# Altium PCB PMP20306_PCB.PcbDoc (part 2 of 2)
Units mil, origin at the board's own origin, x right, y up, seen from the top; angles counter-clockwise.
Board outline 1000 x 1500 mil, 4 copper layers (Top Layer, Signal Layer 1, Signal Layer 2, Bottom Layer), stack 42.6 mil thick; 50 components, 30 nets, 132 pads, 42 vias.
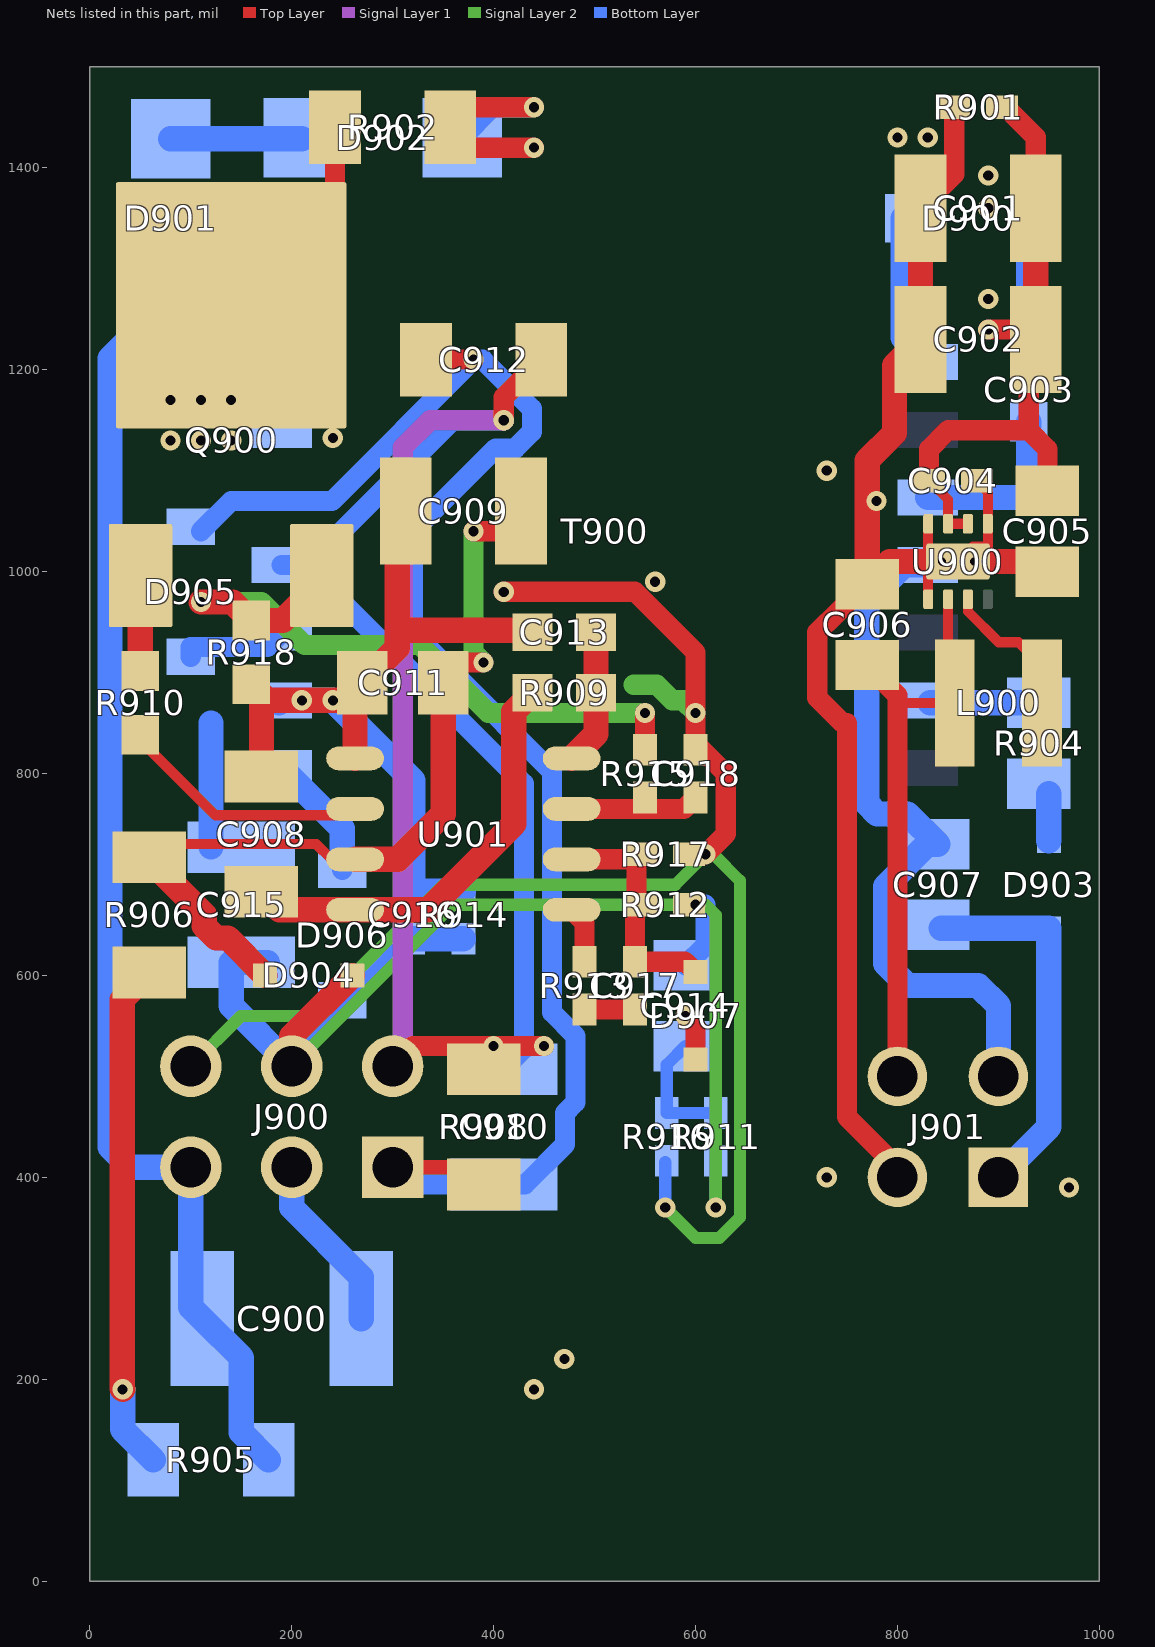
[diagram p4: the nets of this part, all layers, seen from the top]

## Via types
v1: diameter 20, hole 10, Top Layer to Bottom Layer, 40 vias
v2: diameter 19.68, hole 7.87, Top Layer to Bottom Layer, 2 vias

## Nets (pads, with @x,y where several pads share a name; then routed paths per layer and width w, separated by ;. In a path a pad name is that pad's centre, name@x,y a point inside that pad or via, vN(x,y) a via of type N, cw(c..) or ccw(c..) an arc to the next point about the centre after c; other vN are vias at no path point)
5V: C906.1 J901.4 L900.2 U900.6 | length 551.7
  Top Layer w10: 800,877.5 807.5,870 L900.2@856.69,870 ; L900.2@850.16,886.54 U900.6@850.16,972.6
  Top Layer w20: C906.1@780,897.5 800,877.5 J901.4@800,500
12VPH: C910.2 C912.1 D905.1 J900.1 R908.2 | length 1636.9
  Top Layer w14: J900.1@300,410 392.91,410 R908.2@410,392.91
  Top Layer w20: C912.1@332.91,1210 v1(380,1210)
  Bottom Layer w20: D905.1@110,1040 140,1070 240,1070 v1(380,1210) 389.42,1210 437.87,1161.55 437.87,1138.45 421.55,1122.13 402.13,1122.13 320,1040 320,940 410,850 410,849.42 457.87,801.55 457.87,563.23 481.02,540.08 481.02,474.09 470.55,463.62 470.55,432.44 431.03,392.91 C910.2@410,392.91 317.09,392.91 J900.1@300,410
12VPL: C914.1 C915.2 C916.1 D904.2 D906.1 J900.4 R911.2 R912.2 R914.2 | length 1405.1
  Top Layer w25: J900.4@200,510 200,539.76 D904.2@260.24,600
  Signal Layer 2 w12: J900.4@200,510 360,670 610,670 620,660 v1(620,370)
  Bottom Layer w12: v1(620,370) R911.2@620,416.38
  Bottom Layer w20: C914.1@590,610 610,630 610,670
  Bottom Layer w25: C915.2@175.91,612.91 140,612.91 140,570 J900.4@200,510 200,525.53 D906.1@250,575.53 310.85,636.38 R914.2@370,636.38
  other v1: 600,670
B+: C900.1 D901.2 J900.5 R905.1 T900.8 | length 1387.3
  Bottom Layer w25: D901.2@80,1271.26 20,1211.26 20,430 40,410 J900.5@100,410 100,271.26 C900.1@111.26,260 150,221.26 150,147.09 R905.1@177.09,120 ; D901.2@80.63,1270.63 84.5,1274.5 T900.8@190,1274.5
GND_PRI: C900.2 C908.2 C909.1 C911.2 C913.1 C915.1 C916.2 C918.2 J900.3 J900.6 R914.1 R916.1 R917.1 R918.1 T900.2 U901.5 | length 2808.8
  Top Layer w20: v1(410,980) 540,980 600,920 v1(600,860) C918.2@600,823.62 606.38,823.62 630,800 630,740 v1(610,720)
  Top Layer w25: C908.2@170,797.09 R918.1@170,878.5 ; R918.1@176,872.5 v1(240.7,872.5) 252.5,872.5 C911.2@262.72,882.72 ; U901.5@262.72,815 C911.2@262.72,882.72 ; C909.1@304.63,1051.71 304.63,924.63 C911.2@270,890 C911.2@262.72,882.72 ; 312.75,941.87 438.5,941.87 C913.1@438.5,940
  Signal Layer 2 w12: J900.6@100,510 149.76,559.76 220,559.76 350.11,689.87 579.87,689.87 v1(610,720) 617.75,720 643.87,693.87 643.87,360.11 623.76,340 600,340 v1(570,370)
  Signal Layer 2 w20: 538.45,887.87 561.55,887.87 576.92,872.5 587.5,872.5 v1(600,860)
  Bottom Layer w12: v1(570,370) R916.1@570,414.92
  Bottom Layer w25: 120,850 120,727.13 C915.1@120.04,727.09 ; T900.2@187.5,870 T900.2@190,872.5 v1(240.7,872.5) 320,793.2 C916.2@320,683.62 R914.1@370,683.62 ; J900.3@200,410 200,370 268.74,301.26 C900.2@268.74,260
  other v1: 440,190 470,220 210,872.5 560,990
HSS: C910.1 C912.2 J900.2 R908.1 T900.4 | length 1824.6
  Top Layer w20: J900.2@300,510 320,530 v1(400,530) v1(450,530) ; v1(410,1150) 410,1172.91 C912.2@447.09,1210
  Signal Layer 1 w20: J900.2@310,520 310,1122.99 337.01,1150 v1(410,1150)
  Bottom Layer w20: T900.4@190,1006.5 T900.4@213.5,1006.5 ; C910.1@410,507.09 430,527.09 430,790 T900.4@213.5,1006.5 ; v1(410,1150) 359.42,1150 215.92,1006.5 T900.4@213.5,1006.5
NetC901_2: C901.2 C902.2 C903.1 C904.1 C905.1 D900.1 R901.2 U900.2 U900.3 | length 755.6
  Top Layer w10: C904.1@831.38,1090 850,1071.38 850,1047.56 U900.3@850.16,1047.4 U900.2@869.84,1047.4
  Top Layer w20: C904.1@831.38,1090 831.38,1121.38 850,1140 930,1140 ; v1(890,1240) C902.2@927.09,1240 ; R901.2@903.62,1460 907.5,1460 937.09,1430.41 C901.2@937.09,1360 ; C902.2@930,1222.91 930,1140 ; C905.1@948.54,1080 948.54,1121.46 930,1140
  Top Layer w25: C902.2@937.09,1250 C901.2@937.09,1360
  Bottom Layer w25: C903.1@930,1211.5 D900.1@930,1345.53
  other v1: 890,1270 890,1360 890,1392.5
NetC908_1: C908.1 R909.2 U901.8 | length 430.3
  Top Layer w25: C908.1@170,682.91 187.91,665 U901.8@262.72,665 335,665 420,750 420,861.5 R909.2@438.5,880
NetC909_2: C909.2 C911.1 D904.1 R906.2 U901.7 | length 804
  Top Layer w10: R906.2@58.8,717.09 71.71,730 224.33,730 239.33,715 U901.7@262.72,715
  Top Layer w20: C911.1@370,910 v1(390,910) ; v1(380,1040) C909.2@407.09,1040
  Top Layer w25: R906.2@58.8,717.09 58.8,714.82 113.21,660.41 113.21,648.88 125.14,636.95 136.67,636.95 D904.1@173.62,600 ; U901.7@262.72,715 305,715 350,760 C911.1@350,890
  Signal Layer 2 w20: v1(380,1040) 380,920 v1(390,910)
NetC913_2: C913.2 R909.1 U901.4 | length 135
  Top Layer w25: U901.4@477.28,815 501.5,839.21 R909.1@501.5,880 C913.2@501.5,940
NetC914_2: C914.2 D907.2 R911.1 R916.2 | length 170.1
  Top Layer w20: v1(590,560) 600,550 D907.2@600,516.69
  Bottom Layer w12: C914.2@590,530 571.46,511.46 R916.2@571.46,463.62 R911.1@620,463.62
NetC917_1: C917.1 R913.1 | length 50
  Top Layer w20: R913.1@490,566.38 C917.1@540,566.38
NetC917_2: C917.2 D907.1 R912.1 R917.2 U901.2 | length 218.4
  Top Layer w20: U901.2@477.28,715 541.38,715 R912.1@541.38,675 ; R912.1@540,663.62 C917.2@540,613.62 589.68,613.62 D907.1@600,603.31
NetC918_1: C918.1 R915.1 U901.3 | length 127.4
  Top Layer w20: U901.3@477.28,765 588.62,765 C918.1@600,776.38
NetD900_2: D900.2 T900.10 | length 152.6
  Bottom Layer w25: D900.2@805.53,1350 805.53,1231.97 T900.10@830,1207.5
NetD901_1: D901.1 D902.1 | length 130
  Bottom Layer w25: D901.1@80,1428.74 D902.1@210,1428.74
NetD902_2: D902.2 R902.1 | length 209.5
  Top Layer w20: R902.1@377.09,1420 v1(440,1420) ; R902.1@377.09,1460 v1(440,1460)
  Bottom Layer w20: D902.2@368.74,1430 398.74,1460 v1(440,1460)
NetD903_2: D903.2 R904.1 | length 46.7
  Bottom Layer w25: D903.2@950,733.31 R904.1@950,780
NetD905_2: D905.2 T900.3 | length 111.8
  Bottom Layer w20: D905.2@100,915.53 100,925.34 175.84,925.34 T900.3@190,939.5 T900.3@183.88,939.5
NetD906_2: D906.2 T900.1 | length 125.9
  Bottom Layer w20: D906.2@250,704.47 D906.2@250,715
  Bottom Layer w25: T900.1@190,805.5 250,745.5 D906.2@250,715
NetL900_1: L900.1 U900.7 | length 144.6
  Top Layer w10: U900.7@869.84,972.6 869.84,960.47 900.31,930 920,930 943.31,906.69 L900.1@943.31,870
NetQ900_1: Q900.1 R910.2 | length 94.7
  Top Layer w25: R910.2@50,901.5 50,995.91 Q900.1@50.24,996.14
NetQ900_3: Q900.3 R915.2 R918.2 | length 671.6
  Top Layer w20: R915.2@550,823.62 v1(550,860)
  Top Layer w25: v1(110,970) 141.5,970 R918.2@160,951.5 191.5,951.5 229.76,989.76 Q900.3@229.76,996.14
  Signal Layer 2 w20: v1(110,970) 170,970 212.83,927.17 327.46,927.17 394.63,860 v1(550,860)
NetQ900_4: Q900.4 R902.2 T900.6 | length 73.2
  Top Layer w20: Q900.4@242.91,1366.77 R902.2@242.91,1440
  other v1: 80,1130 110,1130 140,1130 240.7,1132.5 80,1170 110,1170 140,1170
NetR904_2: R904.2 T900.15 | length 107.5
  Bottom Layer w25: T900.15@832.5,870 R904.2@940,870
NetR905_2: R905.2 R906.1 | length 491.5
  Top Layer w25: v1(32.5,190) 31.99,190.51 31.99,576.1 R906.1@47.94,592.06
  Bottom Layer w25: v1(32.5,190) 32.5,150.41 R905.2@62.91,120
NetR910_1: R910.1 U901.6 | length 251.7
  Top Layer w10: R910.1@50,838.5 50,832.91 124.29,758.62 256.34,758.62 U901.6@262.72,765
NetR913_2: R913.2 U901.1 | length 56.6
  Top Layer w20: U901.1@477.28,665 490,652.28 R913.2@490,613.62
SGND: C901.1 C902.1 C903.2 C904.2 C905.2 C906.2 C907.1 J901.2 J901.3 R901.1 T900.12 T900.13 U900.1 U900.4 U900.5 U900.9 | length 2373.3
  Top Layer w10: U900.5@830.47,972.6 830.47,1009.53 830,1010 830.47,1010.47 U900.4@830.47,1047.4 ; U900.9@860,1010 874.69,1024.69 889.53,1024.69 U900.1@889.53,1047.4 889.53,1079.09 C904.2@878.62,1090
  Top Layer w20: C906.2@770,987.5 768.76,987.5 731.63,950.38 731.1,950.38 720.63,939.91 720.63,875.1 745.73,850 750,850 750,460 800,410 J901.3@800,400 ; C901.1@822.91,1360 856.38,1393.46 R901.1@856.38,1460
  Top Layer w25: C901.1@822.91,1360 C902.1@822.91,1230 797.09,1204.17 797.09,1137.09 770,1110 C906.2@770,987.5 792.5,1010 830,1010 v2(844.25,1010) U900.9@860,1010 ; v2(875.75,1010) C905.2@938.54,1010
  Bottom Layer w25: T900.13@830,1006.5 806.5,1006.5 769.64,969.64 769.64,770.36 780,760 810,760 C907.1@840,730 830,730 788.13,688.13 788.13,611.87 810,590 880,590 900,570 J901.2@900,500 ; T900.12@830,1073.5 923.5,1073.5 930,1080 C903.2@930,1148.5
  other v1: 970,390 730,400 779.29,1070 730,1100 800,1430 830,1430
VMON: C907.2 D903.1 J901.1 | length 374.1
  Bottom Layer w25: C907.2@843.31,646.69 D903.1@950,646.69 950,450 J901.1@900,400
pads on no net: T900.7 T900.11 T900.14 T900.16 U900.8

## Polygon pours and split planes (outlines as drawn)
GND_PRI on Top Layer "GND_PRI" (solid, remove dead copper, pour order 40): 260,170 230,200 230,280 60,450 60,560 60,920 80,940 150,940 197.48,940 287.48,1030 550,1030 650,930 650,900 650,370 450,170
SGND on Top Layer "SGND" (solid, remove dead copper, pour order 26): 730,370 710,390 710,420 710,1098.5 780,1168.5 780,1430 840,1490 970,1490 990,1470 990,1060 990,390 970,370
5V on Top Layer "5V" (solid, remove dead copper, pour order 24): 850.16,972.6 850,972.44 850,910 850,780 850,670 850,504.25 815.75,470 790,470 770,490 770,520 780,530 780,570 780,897.5 780,921.91 781.91,921.91 800,940 810,950 830,950 840,960 840,970 847.56,970 850.16,972.6
NetL900_1 on Top Layer "L900_1" (solid, remove dead copper, pour order 22): 960,810 930,810 920,810 910,820 900,830 900,870 900,920 870,950 869.84,950.16 869.84,972.6 876.06,972.6 880,968.66 898.66,950 910,950 950,950 960,940
NetC901_2 on Top Layer "C901_2" (solid, remove dead copper, pour order 20): 980,1060 990,1070 990,1220 990,1470 970,1490 940,1490 910,1490 890,1470 890,1460 890,1410 880,1400 880,1380 880,1320 880,1180 820,1120 820,1090 820,1077.56 850,1047.56 850.16,1047.4 869.84,1047.4 869.84,1059.84 870,1060 860,1070 860,1090 860,1101.65 870,1111.65 890,1111.65 898.35,1111.65 950,1060
NetD902_2 on Top Layer "D902_2" (solid, remove dead copper, pour order 4): 320,1470 340,1490 350,1490 450,1490 470,1470 470,1450 470,1410 450,1390 340,1390 320,1410
NetQ900_3 on Top Layer "Q900_3" (solid, remove dead copper, pour order 2): 260,1040 260,950 110,950 100,960 100,980 110,990 160,1040 190,1040
NetQ900_4 on Top Layer "Q900_4" (solid, remove dead copper, pour order 0): 30,1110 10,1130 10,1340 10,1470 30,1490 70,1490 260,1490 280,1470 280,1450 280,1411.73 250.24,1381.97 250,1381.73 250,1350 250,1130 230,1110
SGND on Bottom Layer "SGND" (solid, remove dead copper, pour order 42): 730,370 710,390 710,420 710,1098.5 780,1168.5 780,1430 840,1490 970,1490 990,1470 990,1060 990,390 970,370
GND_PRI on Bottom Layer "GND_PRI" (solid, remove dead copper, pour order 34): 260,170 230,200 230,280 60,450 60,560 60,920 80,940 150,940 270,940 330,1000 340,1010 360,1010 570,1010 650,930 650,900 650,370 450,170
HSS on Bottom Layer "HSS" (solid, remove dead copper, pour order 30): 170,1014.5 170,1030 180,1040 200,1040 234.92,1040 244.92,1050 354.92,1160 390,1160 400,1160 410,1150 410,1140 400,1140 370,1110 340,1080 304.63,1044.63 304.63,980 304.63,933.92 320,918.54 440,798.54 440,620 440,560 460,540 460,516.93 460,500 450,490 400,490 390,480 330,480 280,480 270,490 270,520 290,540 320,540 350,540 410,600 410,700 410,761.46 310,861.46 170,1001.46 170,1006.5
GND_PRI on Bottom Layer "GND_PRI" (solid, remove dead copper, pour order 28): 240,190 230,200 230,210 230,280 50,460 50,630 50,881.3 68.7,900 160,900 240,900 330,810 380,760 380,673.78 380,670 240,530 240,400 240,380 250,370 284.49,335.51 284.49,270 284.49,200 280,195.51 280,200 273.07,193.07 270,190
NetC901_2 on Bottom Layer "C901_2" (solid, remove dead copper, pour order 18): 920,1200 958.54,1200 970,1200 990,1220 990,1240 990,1400 980,1410 890,1410 880,1400 880,1350 880,1221.46 901.46,1200
NetD900_2 on Bottom Layer "D900_2" (solid, remove dead copper, pour order 16): 860,1190 860,1220 860,1340 820,1380 813.07,1380 780,1380 770,1370 770,1360 770,1200 780,1190
12VPL on Bottom Layer "12VPL" (solid, remove dead copper, pour order 14): 180,490 170,500 170,520 130,560 100,590 100,603.07 100,610 140,650 160,650 370,650 380,640 380,630 380,622 370,612 358,600 310,600 240,530 200,490
NetQ900_4 on Bottom Layer "Q900_4" (solid, remove dead copper, pour order 12): 80,1110 70,1120 70,1170 80,1180 90,1180 150,1180 170,1160 230,1160 240,1160 250,1150 250,1140 250,1130 240,1120 230,1110
NetD902_2 on Bottom Layer "D902_2" (solid, remove dead copper, pour order 10): 340,1490 320,1470 320,1460 320,1390 321.5,1390 340,1371.5 390,1371.5 441.5,1371.5 460,1390 460,1400 460,1470 440,1490
NetD901_1 on Bottom Layer "D901_1" (solid, remove dead copper, pour order 8): 30,1490 10,1470 10,1440 10,1410 10,1390 30,1370 40,1370 250,1370 270,1390 270,1404.57 270,1470 250,1490
B+ on Bottom Layer "B+" (solid, remove dead copper, pour order 6): 230,1260 220,1250 200,1250 150,1250 140.08,1250 120,1229.92 90,1229.92 49.92,1229.92 20,1200 10,1200 10,1230 10,1290 10,1310 20,1320 50,1320 220,1320 230,1310
SGND on Signal Layer 1 "SGND" (solid, remove dead copper, pour order 46): 730,370 710,390 710,420 710,1098.5 780,1168.5 780,1430 840,1490 970,1490 990,1470 990,1060 990,390 970,370
GND_PRI on Signal Layer 1 "GND_PRI" (solid, remove dead copper, pour order 38): 260,170 230,200 230,280 60,450 60,560 60,920 80,940 150,940 270,940 330,1000 340,1010 360,1010 570,1010 650,930 650,900 650,370 450,170
HSS on Signal Layer 1 "HSS" (solid, remove dead copper, pour order 32): 420,1170 430,1160 430,1150 430,1140 420,1130 380,1090 360,1070 360,1020 360,698.35 468.35,590 468.35,560 468.35,498.35 450,480 420,480 280,480 270,490 270,510 270,1140 300,1170
SGND on Signal Layer 2 "SGND" (solid, remove dead copper, pour order 44): 730,370 710,390 710,420 710,1098.5 780,1168.5 780,1430 840,1490 970,1490 990,1470 990,1060 990,390 970,370
GND_PRI on Signal Layer 2 "GND_PRI" (solid, remove dead copper, pour order 36): 260,170 230,200 230,280 60,450 60,560 60,920 80,940 150,940 270,940 330,1000 340,1010 360,1010 570,1010 650,930 650,900 650,370 450,170

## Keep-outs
Keep-Out Layer:
  text ".Layer_Name" at 577,-858.49 h60

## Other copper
Top Layer:
  text ".Layer_Name" at 577,-858.49 h60
Bottom Layer:
  text ".Layer_Name" at 577,-858.49 h60

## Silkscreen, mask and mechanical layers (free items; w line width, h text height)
Top Overlay:
  lines w10: 230,650 240,640 300,640 310,630 ; 480,1100 530,1150 530,1220 ; 520,510 520,460 540,440 ; 730,1120 740,1110 740,1070 770,1040 790,1040 ; 730,1160 740,1160 780,1120 ; 970,790 980,800 980,950 ; 460,1290 480,1270 500,1270 510,1260 510,1220 640,1220 680,1260 700,1260 720,1280 720,1370 650,1440 520,1440 460,1380 460,1330 460,1290 ; 490,70 490,310 530,350 530,430 550,450 650,450 660,440 660,70 490,70
  text ".Layer_Name" at 577,-858.49 h60
Bottom Overlay:
  rectangle: 680,10 980,110
  lines w10: 40,530 40,540 60,560 190,560 ; 320,600 320,580 330,570 340,570
  text "'.PRJ_Number'.PCB_Rev-" at 980,130 h108.27
  text ".Layer_Name" at 577,-858.49 h60
Top Paste:
  text ".Layer_Name" at 577,-858.49 h60
Bottom Paste:
  text ".Layer_Name" at 577,-858.49 h60
Top Solder:
  text ".Layer_Name" at 577,-858.49 h60
  text ".Layer_Name" at 577,-858.49 h60
Bottom Solder:
  text ".Layer_Name" at 577,-858.49 h60
Drill Guide:
  text ".Layer_Name" at 577,-858.49 h60
M1 Board Outline:
  the board outline again, w7
  text ".Layer_Name" at 577,-858.49 h60
M2 Board Dimensions:
  rectangle: 0,-275 125,-150
  rectangle: 125,-400 500,-275
  lines w7: 0,-275 1000,-275 ; 125,-400 125,-150 ; 250,-400 250,-150 ; 500,-400 500,-150 ; 750,-400 750,-150 ; 0,-400 1000,-400 1000,-150 0,-150 0,-400
  text ".Layer_Name" at 577,-858.49 h60
M3 3D STEP Top:
  text ".Layer_Name" at 577,-858.49 h60
M4 3D STEP Bottom:
  text ".Layer_Name" at 577,-858.49 h60
M5 Assembly Top:
  lines w10: -292,-930.17 6308,-930.17 ; -292,-726.83 6310,-726.83 ; -292,-523.5 -292,-1133.5 3713,-1133.5 6310,-1133.5 6310,-523.5 -291.5,-523.5 -291.5,-1133.5 1284,-1133.5 ; 2173,-1133.5 2173,-523.5 ; 3440,-726.83 3440,-523.5 ; 4280,-726.83 4280,-523.5 ; 4902,-1140 4902,-937.17
  text "COMPONENTS MARKED 'DNP' SHOULD NOT BE POPULATED." at 1153.5,-318.5 h60
  text "ASSEMBLY VARIANT:" at 1153,-434 h60
  text ".VariantName" at 2189,-434 h60
  text "PCB VIEWED FROM TOP SIDE" at -228.5,-655.67 h60
  text "BOARD #:" at 2248,-655.67 h60
  text ".PRJ_Number" at 2793.5,-655.67 h60
  text "REV:" at 3638,-655.67 h60
  text ".PCB_Rev" at 3929.5,-655.67 h60
  text "SVN REV:" at 4476,-655.67 h60
  text ".VersionControl_RevNumber" at 4982,-655.67 h60
  text "TID #:" at 2248,-859 h60
  text ".TID" at 2793.5,-859 h60
  text "PLOT NAME =" at -228.5,-1064.34 h60
  text ".plot_File_Name" at 577,-1064.34 h60
  text "GENERATED    :" at 2250,-1064.34 h60
  text ".Print_Date" at 3119.5,-1064.34 h60
  text ".Print_Time" at 3848.5,-1064.34 h60
  text "TEXAS INSTRUMENTS" at 5113,-1064.34 h60
M6 Assembly Bottom:
  lines w10: -292.5,-727.33 6309.5,-727.33 ; -290.5,-930.67 6309.5,-930.67 ; 1115.5,-1140.5 1115.5,-937.67 ; 1737.5,-727.33 1737.5,-524 ; 2577.5,-727.33 2577.5,-524 ; 3844.5,-1134 3844.5,-524 ; 4733.5,-1134 6309,-1134 6309,-524 -292.5,-524 -292.5,-1134 2304.5,-1134 6309.5,-1134 6309.5,-524
  text "COMPONENTS MARKED 'DNP' SHOULD NOT BE POPULATED." at 6102,-318 h60
  text ".VariantName" at 5058,-434 h60
  text "ASSEMBLY VARIANT:" at 6097,-434 h60
  text ".VersionControl_RevNumber" at 1035.5,-656.17 h60
  text "SVN REV:" at 1541.5,-656.17 h60
  text ".PCB_Rev" at 2088,-656.17 h60
  text "REV:" at 2379.5,-656.17 h60
  text ".PRJ_Number" at 3224,-656.17 h60
  text "BOARD #:" at 3769.5,-656.17 h60
  text "PCB VIEWED FROM BOTTOM SIDE" at 6246,-656.17 h60
  text ".TID" at 3224,-859.5 h60
  text "TID #:" at 3769.5,-859.5 h60
  text "TEXAS INSTRUMENTS" at 904.5,-1064.84 h60
  text ".Print_Time" at 2169,-1064.84 h60
  text ".Print_Date" at 2898,-1064.84 h60
  text "GENERATED    :" at 3767.5,-1064.84 h60
  text ".plot_File_Name" at 5440.5,-1064.84 h60
  text "PLOT NAME =" at 6246,-1064.84 h60
M9 Title Sheet:
  drawing of 57 lines, arcs and shapes, not listed
  text "1" at 739.84,8036.5 h70
  text "2" at 3235.5,8036.5 h70
  text "3" at 5724.84,8036.5 h70
  text "4" at 8231.51,8036.5 h70
  text "5" at 10730.5,8036.5 h70
  text "6" at 13235.5,8036.5 h70
  text "A" at -416.5,6893.5 h70
  text "A" at 14383.5,6893.5 h70
  text "B" at -416.5,4513.5 h70
  text "B" at 14383.5,4513.5 h70
  text "C" at -416.5,2138.5 h70
  text "C" at 14383.5,2138.5 h70
  text "PROJECT TITLE:" at 11343.5,277.5 h45
  text ".PRJ_Title" at 11393.5,144.17 h70
  text "DESIGNED FOR:" at 11343.5,-23.5 h45
  text ".PRJ_Customer" at 11393.5,-163.5 h70
  text "D" at -416.5,-231.5 h70
  text "D" at 14383.5,-231.5 h70
  text "FILE NAME:" at 11343.5,-323.5 h45
  text ".PCB_File_Name_No_Path" at 11393.5,-443.5 h70
  text "Texas Instruments (TI) and/or its licensors do not warrant the accuracy or completeness of this specification" at 6374,-605.34 h45
  text "ENGINEER:" at 11343.5,-613.5 h45
  text "LAYOUT BY:" at 12848.5,-613.5 h45
  text "or any information contained therein. TI and/or its licensors do not warrant that this design will meet" at 6329.01,-718 h45
  text ".PRJ_Engineer" at 11393.5,-768.49 h70
  text ".PCB_Layout" at 12899,-768.49 h70
  text "the specifications, will be suitable for your application or fit for any particular purpose, or will operate in" at 6329.01,-830.67 h45
  text ".Layer_Name" at 577,-858.49 h60
  text "ALTIUM DESIGNER VERSION:" at 12848.5,-923.5 h45
  text "an implementation. TI and/or its licensors do not warrant that the design is production worthy. You should" at 6329.01,-943.33 h45
  text "completely validate and test your design implementation to confirm the system functionality for your application." at 6374,-1056 h45
  text ".print_Scale" at 11393.5,-1056.83 h70
  text ".Application_BuildNumber" at 12899,-1056.83 h70
  text "1" at 739.84,-1263.5 h70
  text "2" at 3235.5,-1263.5 h70
  text "3" at 5724.84,-1263.5 h70
  text "4" at 8231.51,-1263.5 h70
  text "5" at 10730.5,-1263.5 h70
  text "6" at 13235.5,-1263.5 h70
M10 Fab Notes:
  drawing of 173 lines, arcs and shapes, not listed
  text "DESIGN INFORMATION" at 12378.02,6201 h60
  text "MIN. TRACK WIDTH:" at 11733.46,6021 h60
  text "10" at 12829.7,6021 h60
  text "MIL" at 12984.46,6021 h60
  text "MIN. CLEARANCE:" at 11733.46,5889 h60
  text "0.2" at 12769.7,5889 h60
  text "mm" at 12984.46,5889 h60
  text "MIN. VIA PAD SIZE:" at 11733.46,5757 h60
  text "20" at 12799.71,5757 h60
  text "MIL" at 12984.46,5757 h60
  text "0.05mm (2MIL)" at 12428.46,5615.29 h60
  text "MINIMUM ANNULAR RING" at 11404.23,5611 h60
  text "EXTERNAL" at 13136.46,5611 h60
  text "PER" at 11604.23,5493 h60
  text "IPC-D-275 CLASS 2 LEVEL C" at 11824.23,5493 h60
  text "MIL, HOLES" at 13312.46,5380.71 h60
  text "+/-" at 12920,5380 h60
  text "+/-" at 13774,5380 h60
  text "REGISTRATION TOLERANCES:" at 11404.23,5375 h60
  text "METAL" at 12604,5375 h60
  text "5" at 13180.2,5375 h60
  text "3" at 14013.2,5375 h60
  text "MIL" at 14129.46,5375 h60
  text "+/-" at 13774,5262 h60
  text "HOLE SIZE TOLERANCE (UNLESS OTHERWISE SPECIFIED):" at 11404.23,5257 h60
  text "3" at 14013.2,5257 h60
  text "MIL" at 14129.46,5257 h60
  text "MATERIAL:" at 11329.46,5047.54 h60
  text "FR-4 High Tg" at 12315.9,4907.21 h60
  text "FR-408" at 11750.46,4898.64 h60
  text "OTHER" at 13238.46,4898.64 h60
  text "X" at 12161,4895 h60
  text "62 MIL (1.6mm) +/-10%" at 12070.56,4735.92 h60
  text "THICKNESS:" at 11404.23,4731.64 h60
  text "X" at 11942.4,4731.64 h60
  text "OTHER" at 13355.46,4731.64 h60
  text "TOLERANCE:" at 11404.23,4573.64 h60
  text "X" at 12243.53,4573.64 h60
  text "ANSI IPC-6012 TYPE 3 CLASS 2" at 12430.48,4573.64 h60
  text "OTHER +/-" at 12430.46,4417.64 h60
  text "BOW & TWIST:" at 11404.23,4260.64 h60
  text "X" at 12243.53,4260.64 h60
  text "ANSI IPC-6012 TYPE 3 CLASS 2" at 12430.48,4260.64 h60
  text "OTHER +/-" at 12430.46,4102.13 h60
  text "DRILLING:" at 11329.46,3963.64 h60
  text "REFERENCE:" at 11404.23,3846.64 h60
  text "X" at 12052.46,3846.64 h60
  text "AS SHOWN" at 12239.46,3846.64 h60
  text "X" at 12953.46,3846.64 h60
  text "NC_DRILL FILES" at 13090.46,3846.64 h60
  text "PTH COPPER THICKNESS:" at 11404.23,3688.64 h60
  text "X" at 12534.46,3688.64 h60
  text "20-30 um" at 12671.46,3688.64 h60
  text "OTHER" at 13388.46,3688.64 h60
  text "BOARD FINISH:" at 11329.46,3529.64 h60
  text "SILKSCREEN:" at 11484.68,3411.64 h60
  text "X" at 12433.46,3411.64 h60
  text "TOP" at 12559.46,3411.64 h60
  text "X" at 12943.46,3411.64 h60
  text "BOTTOM" at 13070.46,3411.64 h60
  text "SILKSCREEN COLOR:" at 11484.68,3244.64 h60
  text "X" at 12432.42,3244.64 h60
  text "WHITE" at 12559.46,3244.64 h60
  text "OTHER" at 13070.46,3244.64 h60
  text "X" at 12563.42,3085.44 h60
  text "GREEN" at 12690.46,3085.44 h60
  text "OTHER" at 13308.46,3085.44 h60
  text "SOLDER RESIST COLOR:" at 11484.68,3074.64 h60
  text "X" at 12563.42,2915.44 h60
  text "MATTE" at 12690.46,2915.44 h60
  text "SEMI-GLOSS" at 13308,2914.8 h60
  text "IMMERSION GOLD (ENIG)" at 12390.46,2726.92 h60
  text "ENEPIG" at 13728,2723.64 h60
  text "SURFACE FINISH:" at 11329.46,2722.64 h60
  text "X" at 12203.51,2722.64 h60
  text "IMM. TIN/SILVER OR EQUIV" at 11659,2565.64 h60
  text "OTHER" at 13090.46,2565.64 h60
  text "ARRAY/PANEL:" at 11329.46,2386.64 h60
  text "CUT AND TRIM PER M1 BOARD OUTLINE" at 12390.46,2382.35 h60
  text "N.C. ROUTE" at 12390.46,2230.64 h60
  text "X" at 13069.46,2230.64 h60
  text "V. SCORE" at 13256.46,2230.64 h60
  text "CERTIFICATION:" at 11329.46,2093.64 h60
  text "MATERIALS AND WORKMANSHIP FOR ALL PCBS" at 12054.46,2093.64 h60
  text "TO MEET OR EXCEED THE REQUIREMENTS OF:" at 12054.46,1995.64 h60
  text "X" at 11680.96,1859.13 h60
  text "ANSI IPC-A-600F CLASS ->" at 11819.96,1859.13 h60
  text "X" at 13459.02,1859.13 h60
  text "2" at 13577.96,1859.14 h60
  text "1" at 13262.96,1857.64 h60
  text "3" at 13931.96,1857.64 h60
  text "X" at 12495.02,1699.64 h60
  text "RoHS" at 12631.96,1699.64 h60
  text "OTHER" at 13276.36,1699.64 h60
  text "PER ORDER" at 13673.42,1699.64 h60
  text "ALL BOARDS MUST MEET OR EXCEED UL94-V0 REQUIREMENTS." at 11357,1534 h60
  text "PCB MUST BEAR THE UL94V-0 UL REGISTERED MATERIAL ID NUMBER" at 11357,1414 h60
  text "ADDITIONAL REQUIREMENTS:" at 11329.46,1240.64 h60
  text "MICROSECTION:" at 11404.23,1125.64 h60
  text "YES" at 12309.96,1125.64 h60
  text "X" at 13050,970 h60
  text "REQUIRED" at 13171.46,969.49 h60
  text "BARE BOARD ELEC. TEST:" at 11404.23,966.64 h60
  text "NONE" at 12709.96,966.64 h60
  text "PER ORDER" at 13763.46,966.64 h60
  text ".Layer_Name" at 577,-858.49 h60
M11 Gerber Information:
  lines w10: -292,-930.17 6308,-930.17 ; -292,-726.83 6310,-726.83 ; -292,-523.5 -292,-1133.5 3713,-1133.5 6310,-1133.5 6310,-523.5 -291.5,-523.5 -291.5,-1133.5 1284,-1133.5 ; 2173,-1133.5 2173,-523.5 ; 3440,-726.83 3440,-523.5 ; 4280,-726.83 4280,-523.5 ; 4902,-1140 4902,-937.17
  text "ALL ARTWORK VIEWED FROM TOP SIDE" at -228.5,-655.67 h60
  text "BOARD #:" at 2248,-655.67 h60
  text ".PRJ_Number" at 2793.5,-655.67 h60
  text "REV:" at 3638,-655.67 h60
  text ".PCB_Rev" at 3929.5,-655.67 h60
  text "SVN REV:" at 4476,-655.67 h60
  text ".VersionControl_RevNumber" at 4982,-655.67 h60
  text "LAYER NAME =" at -228.5,-858.49 h60
  text "TID #:" at 2248,-859 h60
  text ".TID" at 2793.5,-859 h60
  text "PLOT NAME =" at -228.5,-1064.34 h60
  text ".plot_File_Name" at 577,-1064.34 h60
  text "GENERATED    :" at 2250,-1064.34 h60
  text ".Print_Date" at 3119.5,-1064.34 h60
  text ".Print_Time" at 3848.5,-1064.34 h60
  text "TEXAS INSTRUMENTS" at 5113,-1064.34 h60
M12 Stackup:
  drawing of 488 lines, arcs and shapes, not listed
  text "Layer" at 6647.5,7810.7 h60
  text "Name" at 7057.41,7810.7 h60
  text "Material" at 7997.16,7810.7 h60
  text "Thickness" at 8856.92,7810.7 h60
  text "Constant" at 9506.76,7810.7 h60
  text "Board Layer Stack" at 10076.62,7810.7 h60
  text "1" at 6647.5,7690.7 h60
  text "Top Overlay" at 7057.41,7690.7 h60
  text "2" at 6647.5,7570.7 h60
  text "Top Solder" at 7057.41,7570.7 h60
  text "Solder Resist" at 7997.16,7570.7 h60
  text "0.40mil" at 8856.92,7570.7 h60
  text "3.5" at 9506.76,7570.7 h60
  text "3" at 6647.5,7450.7 h60
  text "Top Layer" at 7057.41,7450.7 h60
  text "Copper" at 7997.16,7450.7 h60
  text "1.40mil" at 8856.92,7450.7 h60
  text "4" at 6647.5,7330.7 h60
  text "Dielectric1" at 7057.41,7330.7 h60
  text "8.00mil" at 8856.92,7330.7 h60
  text "4.2" at 9506.76,7330.7 h60
  text "5" at 6647.5,7210.7 h60
  text "Signal Layer 1" at 7057.41,7210.7 h60
  text "Copper" at 7997.16,7210.7 h60
  text "1.40mil" at 8856.92,7210.7 h60
  text "6" at 6647.5,7090.7 h60
  text "Dielectric 3" at 7057.41,7090.7 h60
  text "FR-4" at 7997.16,7090.7 h60
  text "21.00mil" at 8856.92,7090.7 h60
  text "4.2" at 9506.76,7090.7 h60
  text "7" at 6647.5,6970.7 h60
  text "Signal Layer 2" at 7057.41,6970.7 h60
  text "Copper" at 7997.16,6970.7 h60
  text "1.40mil" at 8856.92,6970.7 h60
  text "8" at 6647.5,6850.7 h60
  text "Dielectric 2" at 7057.41,6850.7 h60
  text "8.00mil" at 8856.92,6850.7 h60
  text "4.2" at 9506.76,6850.7 h60
  text "9" at 6647.5,6730.7 h60
  text "Bottom Layer" at 7057.41,6730.7 h60
  text "Copper" at 7997.16,6730.7 h60
  text "1.40mil" at 8856.92,6730.7 h60
  text "10" at 6647.5,6610.7 h60
  text "Bottom Solder" at 7057.41,6610.7 h60
  text "Solder Resist" at 7997.16,6610.7 h60
  text "0.40mil" at 8856.92,6610.7 h60
  text "3.5" at 9506.76,6610.7 h60
  text "11" at 6647.5,6490.7 h60
  text "Bottom Overlay" at 7057.41,6490.7 h60
  text ".Layer_Name" at 577,-858.49 h60
M13 Component Bodies Top:
  text ".Layer_Name" at 577,-858.49 h60
M14 Component Bodies Bottom:
  text ".Layer_Name" at 577,-858.49 h60
M15 Courtyards Top:
  text ".Layer_Name" at 577,-858.49 h60
M16 Courtyards Bottom:
  text ".Layer_Name" at 577,-858.49 h60
Drill Drawing:
  circle w10: c5363.8,3141.62 r27.66
  lines w10: 5336.14,2989.5 5391.46,2989.5 5391.46,3044.82 5336.14,3044.82 5336.14,2989.5 ; 5336.14,3238.42 5363.8,3252.25 5391.46,3238.42 5377.63,3266.08 5391.46,3293.74 5363.8,3279.91 5336.14,3293.74 5349.97,3266.08 5336.14,3238.42
  lines w12: 5286,2952.17 8518.76,2952.17 ; 5286,3325.54 8518.76,3325.54 ; 5624.17,2827.71 5624.17,3450 ; 5956.28,2827.71 5956.28,3450 ; 6593.29,2827.71 6593.29,3450 ; 6852.64,2827.71 6852.64,3450 ; 7228.06,2827.71 7228.06,3450 ; 7951.91,2827.71 7951.91,3450 ; 5286,2827.71 8518.76,2827.71 8518.76,3450 5286,3450 5286,2827.71
  text "Symbol" at 5360.68,3362.88 h72
  text "Quantity" at 5661.51,3362.88 h72
  text "Finished Hole Size" at 5993.62,3362.88 h72
  text "Plated" at 6630.62,3362.88 h72
  text "Hole Type" at 6889.98,3362.88 h72
  text "Drill Layer Pair" at 7265.4,3362.88 h72
  text "Hole Tolerance" at 7989.25,3362.88 h72
  text "2" at 5661.51,3238.42 h60
  text "7.87mil (0.200mm)" at 5993.62,3238.42 h60
  text "PTH" at 6630.62,3238.42 h60
  text "Round" at 6889.98,3238.42 h60
  text "Top Layer - Bottom Layer" at 7265.4,3238.42 h60
  text "40" at 5661.51,3113.96 h60
  text "10.00mil (0.254mm)" at 5993.62,3113.96 h60
  text "PTH" at 6630.62,3113.96 h60
  text "Round" at 6889.98,3113.96 h60
  text "Top Layer - Bottom Layer" at 7265.4,3113.96 h60
  text "10" at 5661.51,2989.5 h60
  text "40.16mil (1.020mm)" at 5993.62,2989.5 h60
  text "PTH" at 6630.62,2989.5 h60
  text "Round" at 6889.98,2989.5 h60
  text "Top Layer - Bottom Layer" at 7265.4,2989.5 h60
  text "52 Total" at 5661.51,2865.04 h60
  text ".Layer_Name" at 577,-858.49 h60
M17 Embedded Cavity:
  text ".Layer_Name" at 577,-858.49 h60
M18 Embedded Assembly:
  text ".Layer_Name" at 577,-858.49 h60
M19 Embedded Keepout:
  text ".Layer_Name" at 577,-858.49 h60

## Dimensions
0,-400 to 1000,-400 on M2 Board Dimensions
0,0 to 0,1500 on M2 Board Dimensions
0,0 to 1000,0 on M2 Board Dimensions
